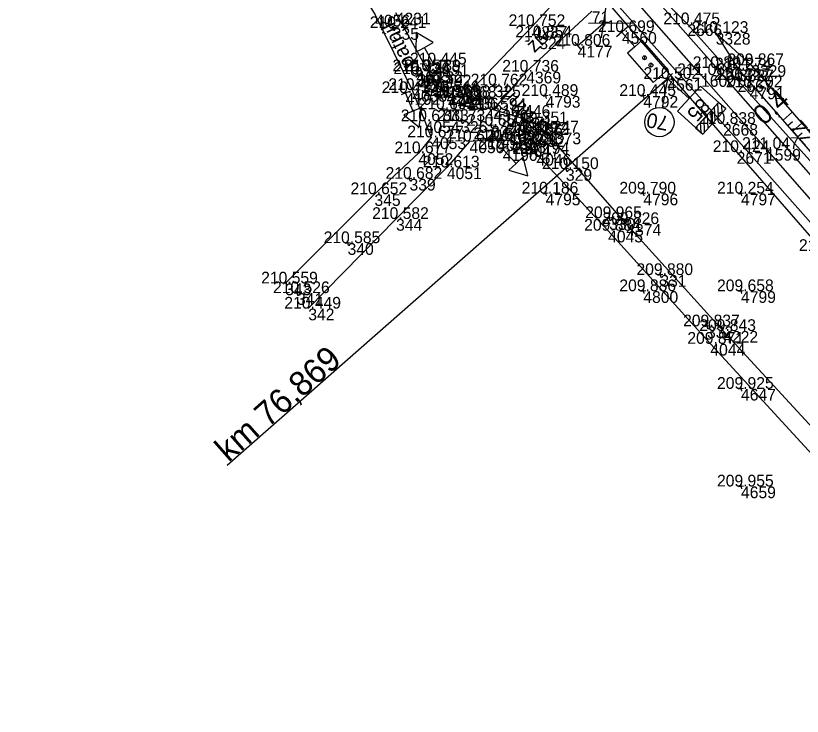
# Model space of a CAD drawing. Extents: x -556590 to -554855, y -1137918 to -1135717.
# Drawn here: x -555284.2 to -555203.7, y -1137013.5 to -1136941.8 of the extents above; entities that cross this region are included whole.
import ezdxf

# ---------------------------------------------------------------- set-up
doc = ezdxf.new("R2010")
doc.units = 0
for name, color, linetype in [('Vrstva 1', 7, 'Continuous'), ('Vrstva 4', 7, 'Continuous'), ('Vrstva 48', 7, 'Continuous'), ('Vrstva 49', 7, 'Continuous'), ('Vrstva 5', 7, 'Continuous'), ('Vrstva 50', 7, 'Continuous'), ('Vrstva 51', 7, 'Continuous'), ('Vrstva 60', 7, 'Continuous'), ('Vrstva 61', 7, 'Continuous'), ('Vrstva 7', 7, 'Continuous')]:
    doc.layers.add(name, color=color, linetype=linetype)

msp = doc.modelspace()

# ---------------------------------------------------------------- linework, layer by layer
at = {"layer": 'Vrstva 1'}
msp.add_lwpolyline([(-555152.803, -1137017.615), (-555159.063, -1137010.489), (-555165.86, -1137002.747), (-555171.844, -1136995.935), (-555178.321, -1136988.571), (-555184.5, -1136981.538), (-555191.36, -1136973.728), (-555198.589, -1136965.499), (-555207.441, -1136955.428), (-555214.089, -1136947.867), (-555220.65, -1136940.399), (-555222.517, -1136938.277), (-555224.963, -1136935.497), (-555231.619, -1136927.933), (-555238.079, -1136920.588), (-555244.97, -1136912.747), (-555251.74, -1136905.051), (-555258.431, -1136897.442), (-555264.06, -1136891.039), (-555271.451, -1136882.637), (-555278.617, -1136874.487), (-555285.485, -1136866.679)], dxfattribs=at)
at = {"layer": 'Vrstva 4'}
for p, q in [((-555223.654, -1136939.495), (-555224.3, -1136944.059)), ((-555226.725, -1136944.861), (-555224.085, -1136942.538)), ((-555225.621, -1136942.558), (-555221.012, -1136942.498)), ((-555227.055, -1136944.486), (-555226.395, -1136945.236))]:
    msp.add_line(p, q, dxfattribs=at)
for points in [[(-555198.389, -1136963.208), (-555212.489, -1136947.146), (-555220.929, -1136937.548), (-555220.369, -1136937.747), (-555215.493, -1136942.659), (-555210.349, -1136948.381), (-555197.709, -1136962.437)], [(-555200.761, -1136965.356), (-555211.836, -1136952.865), (-555222.997, -1136940.28), (-555223.681, -1136940.427), (-555210.442, -1136955.749), (-555201.621, -1136965.878)]]:
    msp.add_lwpolyline(points, dxfattribs=at)
at = {"layer": 'Vrstva 48'}
for p, q in [((-555205.689, -1136952.476), (-555204.755, -1136951.661)), ((-555205.196, -1136953.041), (-555204.729, -1136952.634)), ((-555204.703, -1136953.607), (-555203.769, -1136952.792)), ((-555204.211, -1136954.172), (-555203.743, -1136953.764))]:
    msp.add_line(p, q, dxfattribs=at)
at = {"layer": 'Vrstva 49'}
for p, q in [((-555245.694, -1136942.803), (-555245.6, -1136943.295)), ((-555245.401, -1136943.002), (-555245.893, -1136943.096)), ((-555230.403, -1136943.961), (-555230.895, -1136944.055)), ((-555230.696, -1136943.762), (-555230.602, -1136944.254)), ((-555242.877, -1136947.72), (-555243.369, -1136947.814)), ((-555243.17, -1136947.521), (-555243.076, -1136948.013)), ((-555234.979, -1136948.878), (-555235.471, -1136948.972)), ((-555235.272, -1136948.679), (-555235.178, -1136949.171)), ((-555208.861, -1136949.081), (-555209.353, -1136949.175)), ((-555209.154, -1136948.882), (-555209.06, -1136949.374)), ((-555239.754, -1136949.953), (-555240.246, -1136950.047)), ((-555240.047, -1136949.754), (-555239.953, -1136950.246)), ((-555229.754, -1136949.953), (-555230.246, -1136950.047)), ((-555230.047, -1136949.754), (-555229.953, -1136950.246)), ((-555219.754, -1136949.953), (-555220.246, -1136950.047)), ((-555220.047, -1136949.754), (-555219.953, -1136950.246)), ((-555240.298, -1136951.314), (-555240.79, -1136951.408)), ((-555240.591, -1136951.115), (-555240.497, -1136951.607)), ((-555238.394, -1136952.535), (-555238.886, -1136952.629)), ((-555238.687, -1136952.336), (-555238.593, -1136952.828)), ((-555235.334, -1136953.009), (-555235.826, -1136953.103)), ((-555235.627, -1136952.81), (-555235.533, -1136953.302)), ((-555231.778, -1136953.733), (-555232.27, -1136953.827)), ((-555232.071, -1136953.534), (-555231.977, -1136954.026)), ((-555227.676, -1136957.444), (-555228.168, -1136957.538)), ((-555227.969, -1136957.245), (-555227.875, -1136957.737)), ((-555243.982, -1136958.244), (-555243.888, -1136958.736)), ((-555243.689, -1136958.443), (-555244.181, -1136958.537)), ((-555230.047, -1136959.754), (-555229.953, -1136960.246)), ((-555220.047, -1136959.754), (-555219.953, -1136960.246)), ((-555210.047, -1136959.754), (-555209.953, -1136960.246)), ((-555229.754, -1136959.953), (-555230.246, -1136960.047)), ((-555219.754, -1136959.953), (-555220.246, -1136960.047)), ((-555209.754, -1136959.953), (-555210.246, -1136960.047)), ((-555223.541, -1136962.273), (-555223.447, -1136962.765)), ((-555223.248, -1136962.472), (-555223.74, -1136962.566)), ((-555250.024, -1136965.03), (-555250.516, -1136965.124)), ((-555250.317, -1136964.831), (-555250.223, -1136965.323)), ((-555218.007, -1136968.3), (-555218.499, -1136968.394)), ((-555218.3, -1136968.101), (-555218.206, -1136968.593)), ((-555255.206, -1136970.152), (-555255.698, -1136970.246)), ((-555255.499, -1136969.953), (-555255.405, -1136970.445)), ((-555219.754, -1136969.953), (-555220.246, -1136970.047)), ((-555220.047, -1136969.754), (-555219.953, -1136970.246)), ((-555209.754, -1136969.953), (-555210.246, -1136970.047)), ((-555210.047, -1136969.754), (-555209.953, -1136970.246)), ((-555213.524, -1136973.356), (-555213.43, -1136973.848)), ((-555213.231, -1136973.555), (-555213.723, -1136973.649)), ((-555209.754, -1136979.953), (-555210.246, -1136980.047)), ((-555210.047, -1136979.754), (-555209.953, -1136980.246)), ((-555209.754, -1136989.953), (-555210.246, -1136990.047)), ((-555210.047, -1136989.754), (-555209.953, -1136990.246))]:
    msp.add_line(p, q, dxfattribs=at)
for points in [[(-555196.954, -1136962.492), (-555210.21, -1136947.293), (-555212.593, -1136943.546)], [(-555212.593, -1136943.546), (-555208.954, -1136946.847), (-555195.882, -1136961.835)]]:
    msp.add_lwpolyline(points, dxfattribs=at)
at = {"layer": 'Vrstva 5'}
for p, q in [((-555217.03, -1136947.704), (-555218.04, -1136948.814)), ((-555217.535, -1136948.259), (-555262.61, -1136987.86)), ((-555216.798, -1136948.396), (-555218.272, -1136948.122)), ((-555217.535, -1136948.259), (-555218.082, -1136951.209)), ((-555215.316, -1136950.278), (-555217.535, -1136948.259)), ((-555212.293, -1136952.155), (-555212.359, -1136950.743)), ((-555211.936, -1136951.763), (-555211.974, -1136950.951)), ((-555213.006, -1136952.94), (-555213.073, -1136951.527)), ((-555212.649, -1136952.548), (-555212.716, -1136951.135)), ((-555211.579, -1136951.371), (-555211.582, -1136951.308)), ((-555213.722, -1136953.727), (-555213.789, -1136952.315)), ((-555213.362, -1136953.332), (-555213.429, -1136951.919)), ((-555214.488, -1136953.396), (-555214.502, -1136953.099)), ((-555214.096, -1136953.752), (-555214.146, -1136952.707))]:
    msp.add_line(p, q, dxfattribs=at)
msp.add_lwpolyline([(-555214.138, -1136948.983), (-555211.549, -1136951.338), (-555213.904, -1136953.927), (-555216.493, -1136951.572), (-555214.138, -1136948.983)], dxfattribs=at)
msp.add_lwpolyline([(-555211.549, -1136951.338), (-555212.289, -1136950.665), (-555214.644, -1136953.254), (-555213.904, -1136953.927)], close=True, dxfattribs=at)
msp.add_circle((-555218.356, -1136952.683), 1.5, dxfattribs=at)
at = {"layer": 'Vrstva 50'}
for p, q in [((-555243.28, -1136947.473), (-555243.18, -1136947.473)), ((-555231.651, -1136954.021), (-555231.551, -1136954.021))]:
    msp.add_line(p, q, dxfattribs=at)
for centre in [(-555243.23, -1136947.473), (-555231.601, -1136954.021)]:
    msp.add_circle(centre, 0.5, dxfattribs=at)
at = {"layer": 'Vrstva 51'}
for p, q in [((-555241.867, -1136947.018), (-555240.991, -1136946.536)), ((-555243.867, -1136949.522), (-555244.797, -1136949.892)), ((-555234.022, -1136955.114), (-555234.754, -1136955.796))]:
    msp.add_line(p, q, dxfattribs=at)
for points in [[(-555299.492, -1136878.918), (-555290.703, -1136888.268), (-555273.725, -1136906.431), (-555263.504, -1136917.43), (-555261.757, -1136919.515), (-555259.663, -1136922.519), (-555251.278, -1136935.449), (-555247.444, -1136941.68), (-555243.648, -1136949.393), (-555242.376, -1136952.592), (-555241.711, -1136954.243), (-555243.026, -1136955.871), (-555247.522, -1136960.065), (-555256.664, -1136969.21)], [(-555227.625, -1136938.751), (-555231.344, -1136942.847), (-555238.376, -1136950.189), (-555238.992, -1136950.133), (-555240.136, -1136949.619), (-555240.957, -1136949.014), (-555242.038, -1136947.471), (-555245.343, -1136941.476)], [(-555172.327, -1137017.275), (-555191.864, -1136995.745), (-555211.821, -1136974.075), (-555221.736, -1136963.124), (-555229.945, -1136953.75), (-555231.166, -1136952.8), (-555232.874, -1136952.135), (-555235.334, -1136951.434), (-555231.988, -1136947.517), (-555225.282, -1136941.334)], [(-555241.429, -1136946.777), (-555242.395, -1136945.026), (-555241.519, -1136944.543), (-555243.239, -1136943.493), (-555243.27, -1136945.508), (-555242.395, -1136945.026)], [(-555244.332, -1136949.707), (-555243.593, -1136951.565), (-555244.522, -1136951.935), (-555242.946, -1136953.192), (-555242.664, -1136951.196), (-555243.593, -1136951.565)], [(-555106.827, -1137103.209), (-555101.481, -1137098.096), (-555108.132, -1137090.546), (-555122.012, -1137075.348), (-555136.05, -1137059.997), (-555146.035, -1137048.936), (-555160.294, -1137033.391), (-555175.97, -1137016.16), (-555195.056, -1136995.091), (-555213.136, -1136975.387), (-555223.605, -1136963.802), (-555230.94, -1136955.939), (-555232.118, -1136955.037), (-555233.547, -1136954.632), (-555234.935, -1136954.442), (-555237.794, -1136954.661), (-555240.108, -1136957.322), (-555245.31, -1136962.604), (-555254.296, -1136971.783)], [(-555234.388, -1136955.455), (-555233.024, -1136956.917), (-555233.755, -1136957.6), (-555231.83, -1136958.197), (-555232.293, -1136956.235), (-555233.024, -1136956.917)]]:
    msp.add_lwpolyline(points, dxfattribs=at)
at = {"layer": 'Vrstva 60'}
for p, q in [((-555231.344, -1136942.847), (-555231.344, -1136942.847)), ((-555215.493, -1136942.659), (-555215.493, -1136942.659)), ((-555245.647, -1136943.049), (-555245.647, -1136943.049)), ((-555222.191, -1136943.461), (-555222.191, -1136943.461)), ((-555212.593, -1136943.546), (-555212.593, -1136943.546)), ((-555230.649, -1136944.008), (-555230.649, -1136944.008)), ((-555226.725, -1136944.861), (-555226.725, -1136944.861)), ((-555241.429, -1136946.777), (-555241.429, -1136946.777)), ((-555208.954, -1136946.847), (-555208.954, -1136946.847)), ((-555243.23, -1136947.473), (-555243.23, -1136947.473)), ((-555243.123, -1136947.767), (-555243.123, -1136947.767)), ((-555242.038, -1136947.471), (-555242.038, -1136947.471)), ((-555231.988, -1136947.517), (-555231.988, -1136947.517)), ((-555212.489, -1136947.146), (-555212.489, -1136947.146)), ((-555210.21, -1136947.293), (-555210.21, -1136947.293)), ((-555217.535, -1136948.259), (-555217.535, -1136948.259)), ((-555214.089, -1136947.867), (-555214.089, -1136947.867)), ((-555210.349, -1136948.381), (-555210.349, -1136948.381)), ((-555243.648, -1136949.393), (-555243.648, -1136949.393)), ((-555240.957, -1136949.014), (-555240.957, -1136949.014)), ((-555235.225, -1136948.925), (-555235.225, -1136948.925)), ((-555209.107, -1136949.128), (-555209.107, -1136949.128)), ((-555244.332, -1136949.707), (-555244.332, -1136949.707)), ((-555240.136, -1136949.619), (-555240.136, -1136949.619)), ((-555240, -1136950), (-555240, -1136950)), ((-555238.992, -1136950.133), (-555238.992, -1136950.133)), ((-555238.376, -1136950.189), (-555238.376, -1136950.189)), ((-555230, -1136950), (-555230, -1136950)), ((-555220, -1136950), (-555220, -1136950)), ((-555240.544, -1136951.361), (-555240.544, -1136951.361)), ((-555235.334, -1136951.434), (-555235.334, -1136951.434)), ((-555242.376, -1136952.592), (-555242.376, -1136952.592)), ((-555238.64, -1136952.582), (-555238.64, -1136952.582)), ((-555232.874, -1136952.135), (-555232.874, -1136952.135)), ((-555235.58, -1136953.056), (-555235.58, -1136953.056)), ((-555231.166, -1136952.8), (-555231.166, -1136952.8)), ((-555211.836, -1136952.865), (-555211.836, -1136952.865)), ((-555232.024, -1136953.78), (-555232.024, -1136953.78)), ((-555231.601, -1136954.021), (-555231.601, -1136954.021)), ((-555229.945, -1136953.75), (-555229.945, -1136953.75)), ((-555241.711, -1136954.243), (-555241.711, -1136954.243)), ((-555237.794, -1136954.661), (-555237.794, -1136954.661)), ((-555234.935, -1136954.442), (-555234.935, -1136954.442)), ((-555233.547, -1136954.632), (-555233.547, -1136954.632)), ((-555234.388, -1136955.455), (-555234.388, -1136955.455)), ((-555232.118, -1136955.037), (-555232.118, -1136955.037)), ((-555210.442, -1136955.749), (-555210.442, -1136955.749)), ((-555207.441, -1136955.428), (-555207.441, -1136955.428)), ((-555243.026, -1136955.871), (-555243.026, -1136955.871)), ((-555230.94, -1136955.939), (-555230.94, -1136955.939)), ((-555240.108, -1136957.322), (-555240.108, -1136957.322)), ((-555227.922, -1136957.491), (-555227.922, -1136957.491)), ((-555243.935, -1136958.49), (-555243.935, -1136958.49)), ((-555247.522, -1136960.065), (-555247.522, -1136960.065)), ((-555230, -1136960), (-555230, -1136960)), ((-555220, -1136960), (-555220, -1136960)), ((-555210, -1136960), (-555210, -1136960)), ((-555245.31, -1136962.604), (-555245.31, -1136962.604)), ((-555223.494, -1136962.519), (-555223.494, -1136962.519)), ((-555223.605, -1136963.802), (-555223.605, -1136963.802)), ((-555221.736, -1136963.124), (-555221.736, -1136963.124)), ((-555250.27, -1136965.077), (-555250.27, -1136965.077)), ((-555218.253, -1136968.347), (-555218.253, -1136968.347)), ((-555256.664, -1136969.21), (-555256.664, -1136969.21)), ((-555255.452, -1136970.199), (-555255.452, -1136970.199)), ((-555220, -1136970), (-555220, -1136970)), ((-555210, -1136970), (-555210, -1136970)), ((-555254.296, -1136971.783), (-555254.296, -1136971.783)), ((-555213.477, -1136973.602), (-555213.477, -1136973.602)), ((-555211.821, -1136974.075), (-555211.821, -1136974.075)), ((-555213.136, -1136975.387), (-555213.136, -1136975.387)), ((-555210, -1136980), (-555210, -1136980)), ((-555210, -1136990), (-555210, -1136990))]:
    msp.add_line(p, q, dxfattribs=at)
at = {"layer": 'Vrstva 7'}
for p, q in [((-555221.628, -1136942.966), (-555222.754, -1136943.956)), ((-555219.885, -1136946.287), (-555219.86, -1136945.892)), ((-555219.232, -1136947.039), (-555219.207, -1136946.643))]:
    msp.add_line(p, q, dxfattribs=at)
msp.add_lwpolyline([(-555222.191, -1136943.461), (-555220.871, -1136944.964), (-555221.622, -1136945.624), (-555218.982, -1136948.629), (-555217.48, -1136947.309), (-555220.12, -1136944.303), (-555220.871, -1136944.964)], dxfattribs=at)
for centre in [(-555219.881, -1136946.09), (-555219.221, -1136946.842)]:
    msp.add_circle(centre, 0.2, dxfattribs=at)

# ---------------------------------------------------------------- texts
at = {"layer": 'Vrstva 48'}
msp.add_text('0,4', height=2, rotation=41.09372, dxfattribs=at).set_placement((-555207.679, -1136953.098))
at = {"layer": 'Vrstva 5'}
for s, height, rotation, p in [('85', 1.5, 227.71149, (-555214.142, -1136950.102)), ('70', 1.5, 169.4847, (-555217.321, -1136952.112)), ('km 76,869', 2.5, 41.30087, (-555262.466, -1136987.59))]:
    msp.add_text(s, height=height, rotation=rotation, dxfattribs=at).set_placement(p)
at = {"layer": 'Vrstva 50'}
for s, rotation, p in [('patník', 116.20439, (-555243.366, -1136946.722)), ('patník', 131.30087, (-555230.344, -1136952.787)), ('poškozená ZZ', 131.31416, (-555195.515, -1136961.921))]:
    msp.add_text(s, height=1.5, rotation=rotation, dxfattribs=at).set_placement(p)
at = {"layer": 'Vrstva 51'}
msp.add_text('živ.', height=1.5, rotation=44.01986, dxfattribs=at).set_placement((-555231.156, -1136945.651))
at = {"layer": 'Vrstva 60'}
for s, p in [('71', (-555225.282, -1136942.534)), ('4056', (-555247.444, -1136942.88)), ('4231', (-555245.343, -1136942.676)), ('4237', (-555231.344, -1136944.047)), ('2666', (-555215.493, -1136943.859)), ('335', (-555245.647, -1136944.249)), ('4560', (-555222.191, -1136944.661)), ('3328', (-555212.593, -1136944.746)), ('324', (-555230.649, -1136945.208)), ('4177', (-555226.725, -1136946.061)), ('4191', (-555241.429, -1136947.977)), ('3329', (-555208.954, -1136948.047)), ('4633', (-555243.23, -1136948.673)), ('334', (-555243.123, -1136948.967)), ('4232', (-555242.038, -1136948.671)), ('4369', (-555231.988, -1136948.717)), ('2664', (-555212.489, -1136948.346)), ('3327', (-555210.21, -1136948.493)), ('4561', (-555217.535, -1136949.459)), ('1600', (-555214.089, -1136949.067)), ('2667', (-555210.349, -1136949.581)), ('4055', (-555243.648, -1136950.593)), ('4233', (-555240.957, -1136950.214)), ('325', (-555235.225, -1136950.125)), ('4791', (-555209.107, -1136950.328)), ('4192', (-555244.332, -1136950.907)), ('4234', (-555240.136, -1136950.819)), ('4794', (-555240, -1136951.2)), ('4235', (-555238.992, -1136951.333)), ('4236', (-555238.376, -1136951.389)), ('4793', (-555230, -1136951.2)), ('4792', (-555220, -1136951.2)), ('333', (-555240.544, -1136952.561)), ('4370', (-555235.334, -1136952.634)), ('4054', (-555242.376, -1136953.792)), ('326', (-555238.64, -1136953.782)), ('4371', (-555232.874, -1136953.335)), ('327', (-555235.58, -1136954.256)), ('4372', (-555231.166, -1136954)), ('2668', (-555211.836, -1136954.065)), ('4053', (-555241.711, -1136955.443)), ('328', (-555232.024, -1136954.98)), ('4632', (-555231.601, -1136955.221)), ('4373', (-555229.945, -1136954.95)), ('4050', (-555237.794, -1136955.861)), ('4049', (-555234.935, -1136955.642)), ('4048', (-555233.547, -1136955.832)), ('4047', (-555232.118, -1136956.237)), ('4190', (-555234.388, -1136956.655)), ('2671', (-555210.442, -1136956.949)), ('1599', (-555207.441, -1136956.628)), ('4052', (-555243.026, -1136957.071)), ('4046', (-555230.94, -1136957.139)), ('4051', (-555240.108, -1136958.522)), ('329', (-555227.922, -1136958.691)), ('339', (-555243.935, -1136959.69)), ('345', (-555247.522, -1136961.265)), ('4795', (-555230, -1136961.2)), ('4796', (-555220, -1136961.2)), ('4797', (-555210, -1136961.2)), ('344', (-555245.31, -1136963.804)), ('330', (-555223.494, -1136963.719)), ('4045', (-555223.605, -1136965.002)), ('4374', (-555221.736, -1136964.324)), ('340', (-555250.27, -1136966.277)), ('331', (-555218.253, -1136969.547)), ('343', (-555256.664, -1136970.41)), ('341', (-555255.452, -1136971.399)), ('4800', (-555220, -1136971.2)), ('4799', (-555210, -1136971.2)), ('342', (-555254.296, -1136972.983)), ('332', (-555213.477, -1136974.802)), ('4222', (-555211.821, -1136975.275)), ('4044', (-555213.136, -1136976.587)), ('4647', (-555210, -1136981.2)), ('4659', (-555210, -1136991.2))]:
    msp.add_text(s, height=1.2, dxfattribs=at).set_placement(p)
at = {"layer": 'Vrstva 61'}
for s, p in [('210.241', (-555248.004, -1136943.049)), ('210.752', (-555233.792, -1136942.847)), ('210.475', (-555217.949, -1136942.659)), ('210.854', (-555233.1, -1136944.008)), ('210.699', (-555224.645, -1136943.461)), ('210.123', (-555215.045, -1136943.546)), ('210.806', (-555229.177, -1136944.861)), ('210.445', (-555243.885, -1136946.777)), ('210.824', (-555214.94, -1136947.146)), ('210.274', (-555212.661, -1136947.293)), ('209.867', (-555211.406, -1136946.847)), ('210.357', (-555245.682, -1136947.473)), ('210.436', (-555245.575, -1136947.767)), ('210.439', (-555244.492, -1136947.471)), ('210.736', (-555234.44, -1136947.517)), ('211.084', (-555216.54, -1136947.867)), ('210.762', (-555237.673, -1136948.925)), ('210.502', (-555219.983, -1136948.259)), ('210.327', (-555212.801, -1136948.381)), ('210.437', (-555246.784, -1136949.707)), ('210.450', (-555246.099, -1136949.393)), ('210.492', (-555243.405, -1136949.014)), ('210.544', (-555242.587, -1136949.619)), ('210.202', (-555211.555, -1136949.128)), ('210.569', (-555242.454, -1136950)), ('210.668', (-555241.446, -1136950.133)), ('210.668', (-555240.83, -1136950.189)), ('210.489', (-555232.454, -1136950)), ('210.445', (-555222.456, -1136950)), ('210.695', (-555243, -1136951.361)), ('210.594', (-555237.785, -1136951.434)), ('210.446', (-555235.326, -1136952.135)), ('210.677', (-555244.828, -1136952.592)), ('210.734', (-555241.091, -1136952.582)), ('210.351', (-555233.523, -1136952.8)), ('210.838', (-555214.29, -1136952.865)), ('210.660', (-555238.031, -1136953.056)), ('210.419', (-555234.478, -1136953.78)), ('210.247', (-555232.397, -1136953.75)), ('210.677', (-555244.163, -1136954.243)), ('210.549', (-555237.389, -1136954.442)), ('210.395', (-555236.003, -1136954.632)), ('210.366', (-555234.053, -1136954.021)), ('210.620', (-555240.245, -1136954.661)), ('210.329', (-555234.572, -1136955.037)), ('211.047', (-555209.893, -1136955.428)), ('210.677', (-555245.478, -1136955.871)), ('210.529', (-555236.842, -1136955.455)), ('210.194', (-555233.391, -1136955.939)), ('210.424', (-555212.893, -1136955.749)), ('210.613', (-555242.56, -1136957.322)), ('210.150', (-555230.373, -1136957.491)), ('210.682', (-555246.383, -1136958.49)), ('210.652', (-555249.97, -1136960.065)), ('210.186', (-555232.452, -1136960)), ('209.790', (-555222.451, -1136960)), ('210.254', (-555212.451, -1136960)), ('210.582', (-555247.758, -1136962.604)), ('209.965', (-555225.95, -1136962.519)), ('209.826', (-555224.188, -1136963.124)), ('209.884', (-555226.056, -1136963.802)), ('210.585', (-555252.726, -1136965.077)), ('210.433', (-555204.073, -1136965.878)), ('209.880', (-555220.704, -1136968.347)), ('210.559', (-555259.118, -1136969.21)), ('210.526', (-555257.904, -1136970.199)), ('209.886', (-555222.452, -1136970)), ('209.658', (-555212.454, -1136970)), ('210.449', (-555256.75, -1136971.783)), ('209.837', (-555215.929, -1136973.602)), ('209.843', (-555214.273, -1136974.075)), ('209.871', (-555215.493, -1136975.387)), ('209.925', (-555212.456, -1136980)), ('209.955', (-555212.456, -1136990))]:
    msp.add_text(s, height=1.2, dxfattribs=at).set_placement(p)

doc.saveas('drawing.dxf')
